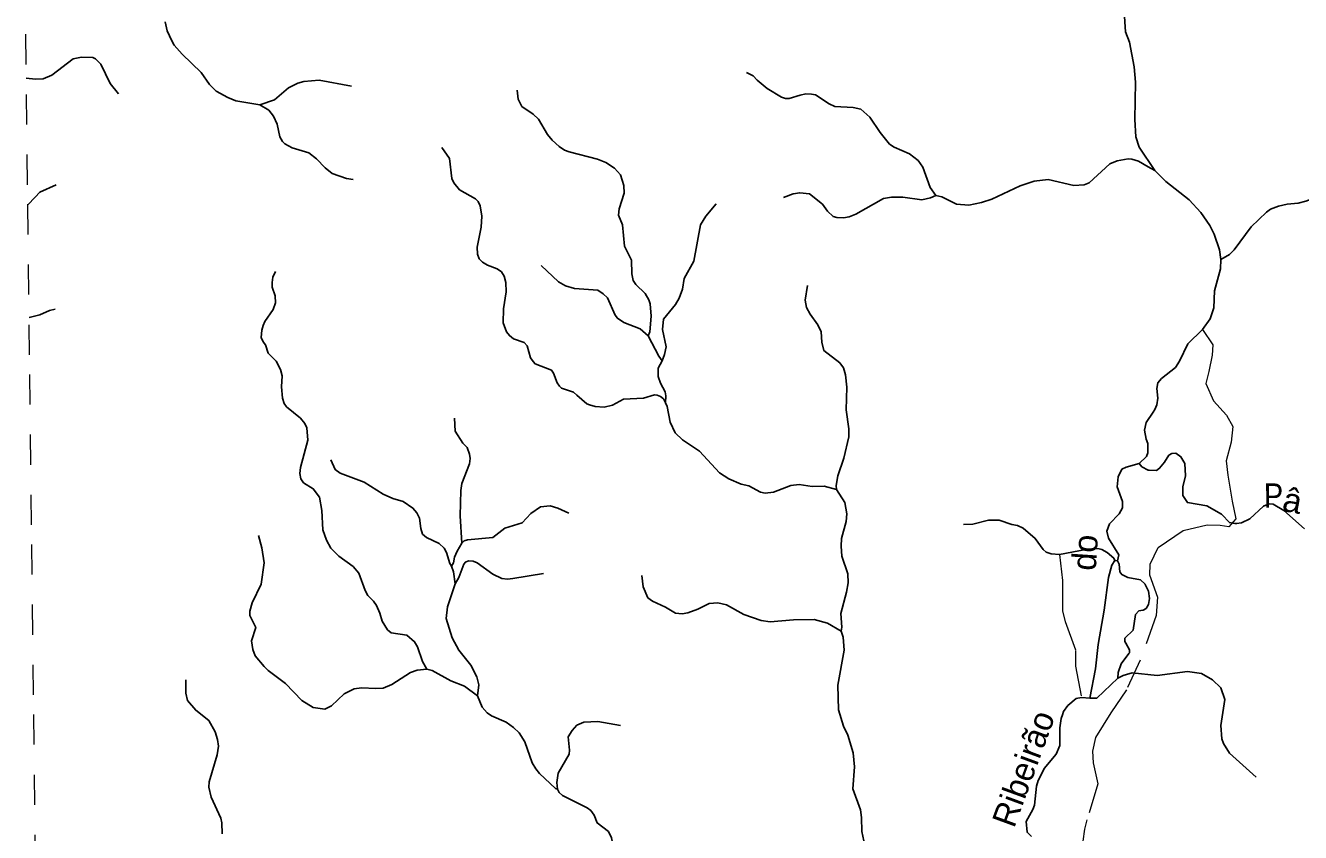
# Model space of a CAD drawing. Extents: x 320.3 to 346.3, y 7455.4 to 7483.3.
# Drawn here: x 320.388 to 324.622, y 7472.999 to 7475.68 of the extents above; entities that cross this region are included whole.
import ezdxf
from ezdxf.enums import TextEntityAlignment as Align

# ---------------------------------------------------------------- set-up
doc = ezdxf.new("R2010")
doc.units = 0
doc.header["$LTSCALE"] = 0.032
doc.linetypes.add('SHORT_DASHED', pattern=[2.7, 1.5, -1.2])
for name, color, linetype, lineweight in [('21', 7, 'SHORT_DASHED', 13), ('53', 7, 'SHORT_DASHED', 13), ('7', 7, 'Continuous', 25)]:
    doc.layers.add(name, color=color, linetype=linetype, lineweight=lineweight)
doc.layers.add('61', color=7, linetype='Continuous')

msp = doc.modelspace()

# ---------------------------------------------------------------- linework, layer by layer
at = {"layer": '21'}
for points in [[(324.2967, 7474.6697), (324.3315, 7474.6194), (324.3296, 7474.5852), (324.3182, 7474.53), (324.3086, 7474.4901), (324.3334, 7474.433), (324.3771, 7474.3854), (324.398, 7474.3474), (324.3923, 7474.296), (324.3752, 7474.2333), (324.3809, 7474.1857), (324.3961, 7474.1001), (324.4075, 7474.0412), (324.3847, 7474.0145), (324.3562, 7474.0183), (324.3125, 7474.0202), (324.2326, 7474.0012), (324.149, 7473.9442), (324.1224, 7473.889), (324.1205, 7473.8548), (324.1471, 7473.7806), (324.1433, 7473.7197), (324.0901, 7473.5714), (324.0445, 7473.4724), (323.9931, 7473.3963), (323.9418, 7473.3145), (323.9323, 7473.2688), (323.9342, 7473.2308), (323.9494, 7473.1604), (323.9133, 7473.0406), (323.9057, 7473.0101), (323.8943, 7472.9302)], [(323.8225, 7473.9227), (323.8321, 7473.8356), (323.8321, 7473.7955), (323.8321, 7473.7337), (323.8414, 7473.6997), (323.8754, 7473.604), (323.8754, 7473.5515), (323.8955, 7473.4469)]]:
    msp.add_lwpolyline(points, dxfattribs=at)
at = {"layer": '53'}
msp.add_lwpolyline([(320.5226, 7464.4161), (320.5159, 7464.9811), (320.5091, 7465.5461), (320.5024, 7466.1111), (320.4957, 7466.6761), (320.489, 7467.2411), (320.4823, 7467.806), (320.4756, 7468.371), (320.4689, 7468.936), (320.4621, 7469.501), (320.4554, 7470.066), (320.4487, 7470.6309), (320.442, 7471.1959), (320.4353, 7471.7609), (320.4286, 7472.3259), (320.4219, 7472.8909), (320.4152, 7473.4558), (320.4085, 7474.0208), (320.4018, 7474.5858), (320.3951, 7475.1508), (320.3884, 7475.7157)], dxfattribs=at)
at = {"layer": '7'}
msp.add_line((324.0056, 7473.9028), (324.0144, 7473.9013), dxfattribs=at)
for points in [[(324.037, 7475.7261), (324.0409, 7475.6592), (324.0545, 7475.6247), (324.0703, 7475.5421), (324.0741, 7475.4921), (324.0724, 7475.3681), (324.0752, 7475.3102), (324.0869, 7475.2757), (324.139, 7475.1987)], [(320.852, 7475.692), (320.8591, 7475.6623), (320.874, 7475.629), (320.8826, 7475.6144), (320.9091, 7475.5843), (320.9717, 7475.5236), (320.9992, 7475.4841), (321.0217, 7475.4612), (321.0601, 7475.4405), (321.0871, 7475.4294), (321.1668, 7475.4168)], [(320.6968, 7475.4532), (320.67, 7475.4869), (320.6384, 7475.5509), (320.6206, 7475.5695), (320.6121, 7475.5741), (320.574, 7475.5743), (320.5468, 7475.569), (320.4754, 7475.5145), (320.4473, 7475.5031), (320.4219, 7475.5011), (320.3909, 7475.5048)], [(321.1668, 7475.4168), (321.2158, 7475.4326), (321.2614, 7475.4731), (321.2928, 7475.4888), (321.313, 7475.4943), (321.3631, 7475.4983), (321.4715, 7475.4782)], [(323.4119, 7475.1155), (323.393, 7475.1416), (323.3685, 7475.209), (323.3528, 7475.2311), (323.3243, 7475.2533), (323.2732, 7475.2754), (323.2577, 7475.2857), (323.2262, 7475.3245), (323.1923, 7475.3748), (323.1621, 7475.4017), (323.1371, 7475.4069), (323.0761, 7475.4111), (323.0577, 7475.4191), (323.0117, 7475.449), (322.9983, 7475.4519), (322.9793, 7475.4526), (322.9606, 7475.4485), (322.9242, 7475.4373), (322.9119, 7475.4377), (322.8985, 7475.4416), (322.8509, 7475.4711), (322.8185, 7475.4988), (322.8047, 7475.5131), (322.7825, 7475.5232)], [(322.4559, 7474.6485), (322.4612, 7474.6621), (322.4664, 7474.7141), (322.4629, 7474.7548), (322.4587, 7474.7686), (322.4463, 7474.79), (322.4156, 7474.8197), (322.4065, 7474.8332), (322.4021, 7474.8551), (322.4003, 7474.9006), (322.3774, 7474.9472), (322.3715, 7475.0175), (322.3576, 7475.0497), (322.36, 7475.0706), (322.3765, 7475.1229), (322.3753, 7475.148), (322.3647, 7475.1843), (322.3445, 7475.2062), (322.316, 7475.2251), (322.2877, 7475.2355), (322.1941, 7475.2604), (322.1781, 7475.2662), (322.1606, 7475.2777), (322.1373, 7475.2993), (322.1224, 7475.3182), (322.0922, 7475.3686), (322.0742, 7475.3853), (322.0361, 7475.4109), (322.0242, 7475.4352), (322.021, 7475.4645)], [(321.1668, 7475.4168), (321.196, 7475.3981), (321.2115, 7475.3784), (321.2236, 7475.3521), (321.2335, 7475.3104), (321.2415, 7475.2945), (321.2495, 7475.2866), (321.2744, 7475.2733), (321.329, 7475.2569), (321.3549, 7475.2374), (321.3832, 7475.2068), (321.4063, 7475.1885), (321.4546, 7475.1715), (321.4764, 7475.1684)], [(322.5142, 7474.4266), (322.5076, 7474.4393), (322.4971, 7474.4473), (322.486, 7474.4521), (322.477, 7474.4531), (322.4403, 7474.4415), (322.3739, 7474.4387), (322.3377, 7474.4184), (322.31, 7474.4115), (322.28, 7474.4141), (322.2612, 7474.4192), (322.2526, 7474.4232), (322.2188, 7474.4521), (322.2083, 7474.4613), (322.1689, 7474.4754), (322.1617, 7474.4813), (322.1545, 7474.4926), (322.1423, 7474.5247), (322.1357, 7474.5343), (322.0809, 7474.5555), (322.0739, 7474.5632), (322.0649, 7474.5759), (322.0541, 7474.6156), (322.0445, 7474.627), (322.0086, 7474.6391), (321.9952, 7474.6498), (321.9854, 7474.6627), (321.9747, 7474.6923), (321.9763, 7474.7383), (321.9846, 7474.7948), (321.9833, 7474.8264), (321.978, 7474.8466), (321.9689, 7474.8613), (321.9551, 7474.8719), (321.9223, 7474.8842), (321.9064, 7474.8932), (321.8954, 7474.9052), (321.8895, 7474.9201), (321.888, 7474.9434), (321.9018, 7475.0099), (321.9035, 7475.0463), (321.8987, 7475.0807), (321.8917, 7475.0948), (321.8828, 7475.1045), (321.8302, 7475.1337), (321.8107, 7475.1575), (321.8041, 7475.1719), (321.7966, 7475.2384), (321.7708, 7475.2746)], [(324.139, 7475.1987), (324.1168, 7475.2106), (324.085, 7475.2292), (324.0622, 7475.2354), (324.0504, 7475.2364), (324.014, 7475.2306), (323.9896, 7475.22), (323.9212, 7475.1571), (323.9043, 7475.1504), (323.8697, 7475.1485), (323.784, 7475.1677), (323.7378, 7475.163), (323.6917, 7475.1472), (323.5979, 7475.1027), (323.5635, 7475.0915), (323.5216, 7475.083), (323.4796, 7475.0864), (323.4315, 7475.1112), (323.4119, 7475.1155)], [(324.139, 7475.1987), (324.175, 7475.1617), (324.2532, 7475.1011), (324.292, 7475.0591), (324.3216, 7475.0149), (324.336, 7474.9861), (324.353, 7474.9342), (324.3579, 7474.9023)], [(320.49, 7475.1507), (320.4364, 7475.126), (320.4202, 7475.1094), (320.3959, 7475.0844)], [(322.9052, 7475.1081), (322.9381, 7475.1206), (322.9596, 7475.1244), (322.9915, 7475.1204), (323.0352, 7475.0863), (323.0519, 7475.0627), (323.0706, 7475.0456), (323.0825, 7475.0418), (323.1054, 7475.0409), (323.1236, 7475.0442), (323.1462, 7475.053), (323.2379, 7475.1046), (323.2641, 7475.1093), (323.3018, 7475.1093), (323.3653, 7475.1008), (323.3935, 7475.1075), (323.4119, 7475.1155)], [(324.3579, 7474.9023), (324.3869, 7474.919), (324.4023, 7474.9342), (324.4588, 7475.0108), (324.5093, 7475.0597), (324.523, 7475.0694), (324.5498, 7475.0802), (324.5778, 7475.0862), (324.6152, 7475.0894), (324.64, 7475.096), (324.7074, 7475.1214), (324.7235, 7475.1318), (324.7492, 7475.1411)], [(322.5031, 7474.5663), (322.5102, 7474.5874), (322.5165, 7474.6128), (322.5041, 7474.6696), (322.5072, 7474.7037), (322.547, 7474.7528), (322.5592, 7474.7742), (322.5701, 7474.8037), (322.5761, 7474.8395), (322.6075, 7474.8969), (322.6305, 7475.0181), (322.6474, 7475.0462), (322.6815, 7475.0872)], [(321.7215, 7473.5414), (321.707, 7473.5669), (321.6907, 7473.6156), (321.6807, 7473.6327), (321.6547, 7473.6539), (321.6027, 7473.6626), (321.5903, 7473.6726), (321.5727, 7473.7005), (321.5654, 7473.727), (321.5537, 7473.7527), (321.5444, 7473.767), (321.5254, 7473.7867), (321.516, 7473.8028), (321.4948, 7473.8601), (321.4769, 7473.8822), (321.4291, 7473.9166), (321.4025, 7473.9434), (321.388, 7473.9705), (321.3761, 7474.0045), (321.373, 7474.0681), (321.3647, 7474.1129), (321.3439, 7474.1406), (321.3116, 7474.161), (321.3029, 7474.1739), (321.299, 7474.1917), (321.302, 7474.2118), (321.3259, 7474.3026), (321.3228, 7474.3429), (321.3163, 7474.3575), (321.3011, 7474.3755), (321.2555, 7474.4133), (321.2479, 7474.4241), (321.2424, 7474.4415), (321.239, 7474.4799), (321.241, 7474.5165), (321.2356, 7474.5371), (321.2212, 7474.5645), (321.1942, 7474.5911), (321.1857, 7474.6187), (321.1779, 7474.6285), (321.1714, 7474.6428), (321.1728, 7474.6673), (321.1772, 7474.6832), (321.1834, 7474.6969), (321.2107, 7474.7368), (321.2186, 7474.7583), (321.2178, 7474.7814), (321.2078, 7474.811), (321.2076, 7474.8256), (321.21, 7474.8437), (321.2189, 7474.8627)], [(322.4559, 7474.6485), (322.4296, 7474.6726), (322.3759, 7474.6934), (322.354, 7474.7074), (322.3465, 7474.7178), (322.3206, 7474.7747), (322.307, 7474.7887), (322.2894, 7474.8009), (322.2112, 7474.8063), (322.1821, 7474.8151), (322.1585, 7474.8281), (322.1007, 7474.882)], [(324.0863, 7474.2242), (324.1106, 7474.2483), (324.1156, 7474.2606), (324.1157, 7474.2909), (324.1097, 7474.3051), (324.1039, 7474.3352), (324.1098, 7474.3607), (324.1328, 7474.395), (324.1392, 7474.4046), (324.1459, 7474.4195), (324.1482, 7474.4413), (324.1451, 7474.4738), (324.1484, 7474.4926), (324.1612, 7474.5071), (324.2071, 7474.544), (324.2209, 7474.5648), (324.2479, 7474.6221), (324.2967, 7474.6697), (324.3229, 7474.7059), (324.3344, 7474.7417), (324.3369, 7474.7987), (324.3568, 7474.8712), (324.3579, 7474.9023)], [(323.0817, 7474.138), (323.0801, 7474.1522), (323.0859, 7474.1835), (323.1064, 7474.2429), (323.1231, 7474.313), (323.1228, 7474.3395), (323.1136, 7474.4026), (323.1159, 7474.4783), (323.1111, 7474.5188), (323.1045, 7474.5424), (323.0924, 7474.5588), (323.0398, 7474.6), (323.0334, 7474.6277), (323.0312, 7474.6621), (323.0199, 7474.6849), (322.9939, 7474.7204), (322.9821, 7474.7431), (322.9779, 7474.7673), (322.9848, 7474.816)], [(320.4868, 7474.738), (320.4677, 7474.7334), (320.4363, 7474.7184), (320.4003, 7474.7099)], [(322.4559, 7474.6485), (322.492, 7474.5814), (322.5031, 7474.5663)], [(322.5031, 7474.5663), (322.4889, 7474.5413), (322.4894, 7474.5135), (322.4976, 7474.4914), (322.5122, 7474.4629), (322.5148, 7474.4499), (322.5142, 7474.4266)], [(323.0817, 7474.138), (323.0406, 7474.1499), (323.0008, 7474.148), (322.958, 7474.1549), (322.9303, 7474.152), (322.8721, 7474.1297), (322.8449, 7474.1265), (322.8289, 7474.13), (322.7902, 7474.1501), (322.7655, 7474.1565), (322.7238, 7474.1738), (322.6933, 7474.194), (322.6266, 7474.2657), (322.5701, 7474.3033), (322.5461, 7474.3271), (322.5296, 7474.3621), (322.5191, 7474.4139), (322.5142, 7474.4266)], [(321.8135, 7474.3752), (321.8155, 7474.3326), (321.8404, 7474.2924), (321.8547, 7474.2775), (321.8632, 7474.2563), (321.8646, 7474.2417), (321.8626, 7474.2238), (321.8377, 7474.1583), (321.8339, 7474.1346), (321.8321, 7474.0512), (321.8373, 7473.96)], [(321.4023, 7474.2368), (321.4172, 7474.2048), (321.4329, 7474.1926), (321.5133, 7474.163), (321.5763, 7474.1234), (321.608, 7474.1084), (321.6428, 7474.0981), (321.6749, 7474.0767), (321.6878, 7474.0607), (321.6966, 7474.0432), (321.7009, 7474.0088), (321.7068, 7473.9905), (321.7204, 7473.9786), (321.7625, 7473.9588), (321.7784, 7473.943), (321.7861, 7473.9292), (321.7971, 7473.8923), (321.8031, 7473.884)], [(324.0863, 7474.2242), (324.0959, 7474.2142), (324.1168, 7474.2028), (324.1195, 7474.2027), (324.1438, 7474.2017), (324.1544, 7474.2089), (324.1714, 7474.2287), (324.1854, 7474.2523), (324.195, 7474.2579), (324.2087, 7474.2588), (324.2251, 7474.2473), (324.2385, 7474.2248), (324.2404, 7474.1842), (324.2321, 7474.1467), (324.2318, 7474.1188), (324.2467, 7474.0949), (324.3112, 7474.0846), (324.3602, 7474.0567), (324.3612, 7474.0556), (324.3865, 7474.0282), (324.4039, 7474.0258), (324.4101, 7474.0249), (324.4268, 7474.028), (324.4539, 7474.0404), (324.4997, 7474.0825), (324.5183, 7474.0909), (324.5317, 7474.0896), (324.5673, 7474.0687), (324.6353, 7474.0078)], [(324.0144, 7473.9013), (324.0191, 7473.9214), (323.9852, 7473.9762), (323.9791, 7474.0002), (323.9886, 7474.0243), (324.0207, 7474.0576), (324.0318, 7474.0777), (324.0311, 7474.0963), (324.031, 7474.0986), (324.0141, 7474.1471), (324.0173, 7474.1805), (324.0297, 7474.2056), (324.0441, 7474.2127), (324.0863, 7474.2242)], [(323.0975, 7473.6679), (323.0998, 7473.6815), (323.096, 7473.7261), (323.1148, 7473.7971), (323.1199, 7473.8287), (323.1189, 7473.8586), (323.0996, 7473.9172), (323.0975, 7473.9499), (323.0986, 7473.9754), (323.1132, 7474.0324), (323.1158, 7474.058), (323.1096, 7474.0951), (323.0817, 7474.138)], [(322.1924, 7474.0598), (322.1557, 7474.0769), (322.1312, 7474.0841), (322.0983, 7474.0807), (322.0668, 7474.0583), (322.0383, 7474.0281), (321.9805, 7474.0104), (321.9399, 7473.9785), (321.8566, 7473.9717), (321.8454, 7473.9681), (321.8373, 7473.96)], [(324.0056, 7473.9028), (324.0024, 7473.9102), (323.9808, 7473.9289), (323.9631, 7473.9387), (323.9499, 7473.942), (323.9495, 7473.9421), (323.91, 7473.9392), (323.8225, 7473.9227), (323.7945, 7473.9247), (323.7778, 7473.9305), (323.7681, 7473.9391), (323.7415, 7473.976), (323.7012, 7474.0104), (323.683, 7474.0184), (323.6638, 7474.0217), (323.622, 7474.036), (323.5866, 7474.037), (323.5343, 7474.0229), (323.5038, 7474.022)], [(321.7215, 7473.5414), (321.6889, 7473.5377), (321.667, 7473.5303), (321.6047, 7473.4908), (321.5757, 7473.4783), (321.5523, 7473.4768), (321.5046, 7473.48), (321.4794, 7473.476), (321.4464, 7473.46), (321.4048, 7473.4194), (321.382, 7473.4085), (321.3441, 7473.4136), (321.3064, 7473.437), (321.252, 7473.4943), (321.1941, 7473.5375), (321.1808, 7473.5506), (321.1513, 7473.5861), (321.1431, 7473.6073), (321.1389, 7473.6358), (321.1532, 7473.6797), (321.1339, 7473.7199), (321.1338, 7473.7337), (321.1412, 7473.7618), (321.1712, 7473.824), (321.1809, 7473.8944), (321.1735, 7473.9447), (321.1618, 7473.9858)], [(321.8373, 7473.96), (321.8216, 7473.9336), (321.8133, 7473.9133), (321.8097, 7473.8946), (321.8031, 7473.884)], [(322.1087, 7473.8595), (322.0067, 7473.8423), (321.989, 7473.8406), (321.9703, 7473.8425), (321.9407, 7473.8568), (321.8879, 7473.8947), (321.8755, 7473.9002), (321.8591, 7473.9011), (321.8493, 7473.8969), (321.8444, 7473.8906), (321.8271, 7473.8461), (321.8153, 7473.8246)], [(323.9232, 7473.4454), (323.9421, 7473.5423), (323.951, 7473.6236), (323.971, 7473.7376), (323.9849, 7473.8464), (323.9962, 7473.8874), (324.0056, 7473.9028)], [(324.0162, 7473.5116), (324.0165, 7473.5307), (324.0269, 7473.5592), (324.0528, 7473.5936), (324.0545, 7473.5958), (324.0543, 7473.6058), (324.042, 7473.6279), (324.0389, 7473.6335), (324.0392, 7473.6442), (324.0668, 7473.6707), (324.0746, 7473.7231), (324.0856, 7473.7348), (324.0991, 7473.7372), (324.0995, 7473.7374), (324.1103, 7473.7431), (324.1179, 7473.7562), (324.1214, 7473.776), (324.1175, 7473.8004), (324.107, 7473.8225), (324.1065, 7473.8235), (324.091, 7473.8381), (324.0494, 7473.8462), (324.0294, 7473.8556), (324.023, 7473.8653), (324.0201, 7473.8907), (324.0144, 7473.9013)], [(321.8153, 7473.8246), (321.8094, 7473.865), (321.8031, 7473.884)], [(323.0975, 7473.6679), (323.052, 7473.6943), (323.0077, 7473.7061), (322.939, 7473.7056), (322.8609, 7473.6992), (322.8316, 7473.7029), (322.7744, 7473.7231), (322.7158, 7473.7557), (322.6871, 7473.7623), (322.6591, 7473.7592), (322.6212, 7473.7406), (322.5876, 7473.7285), (322.5696, 7473.7257), (322.5471, 7473.7279), (322.514, 7473.7476), (322.4702, 7473.7677), (322.4547, 7473.7785), (322.4392, 7473.8153), (322.4346, 7473.8522)], [(321.8153, 7473.8246), (321.79, 7473.7488), (321.7855, 7473.7094), (321.8054, 7473.6458), (321.8278, 7473.6049), (321.8669, 7473.5548), (321.8877, 7473.5163), (321.8944, 7473.4896), (321.8895, 7473.4527)], [(323.1827, 7472.925), (323.1653, 7473.0019), (323.1648, 7473.0483), (323.1611, 7473.0744), (323.136, 7473.1439), (323.1415, 7473.2168), (323.1365, 7473.2634), (323.1193, 7473.3217), (323.1046, 7473.3518), (323.088, 7473.4059), (323.0865, 7473.4886), (323.107, 7473.6045), (323.1035, 7473.6483), (323.0975, 7473.6679)], [(321.8895, 7473.4527), (321.8463, 7473.4846), (321.8005, 7473.503), (321.7391, 7473.5366), (321.7215, 7473.5414)], [(324.0162, 7473.5116), (323.9457, 7473.4449), (323.9232, 7473.4454)], [(324.0162, 7473.5116), (324.0338, 7473.5205), (324.0447, 7473.5238), (324.0633, 7473.5295), (324.1461, 7473.5208), (324.2474, 7473.5342), (324.2941, 7473.5267), (324.3302, 7473.5064), (324.358, 7473.4796), (324.3715, 7473.4404), (324.3575, 7473.3539), (324.3614, 7473.31), (324.367, 7473.2944), (324.3865, 7473.2629), (324.4756, 7473.1829)], [(321.0417, 7472.9946), (321.0408, 7473.0309), (321.0368, 7473.0461), (321.0053, 7473.1159), (320.9977, 7473.149), (320.9983, 7473.1675), (321.0252, 7473.2564), (321.0288, 7473.2858), (321.0262, 7473.3083), (321.0185, 7473.3334), (320.9973, 7473.3709), (320.954, 7473.405), (320.9269, 7473.4371), (320.9204, 7473.4617), (320.9212, 7473.5063)], [(322.1552, 7473.1424), (322.1482, 7473.1454), (322.0948, 7473.1954), (322.0826, 7473.2108), (322.0707, 7473.2308), (322.0462, 7473.3), (322.0281, 7473.3303), (322.0094, 7473.3479), (321.9849, 7473.3649), (321.9363, 7473.3859), (321.9211, 7473.3959), (321.9048, 7473.4151), (321.8895, 7473.4527)], [(323.7291, 7472.9856), (323.7147, 7472.9999), (323.7111, 7473.0359), (323.7337, 7473.0748), (323.7387, 7473.0895), (323.7457, 7473.1524), (323.7517, 7473.1716), (323.7711, 7473.2104), (323.7715, 7473.2112), (323.8107, 7473.2586), (323.8228, 7473.2879), (323.823, 7473.3213), (323.8232, 7473.3462), (323.8281, 7473.378), (323.8322, 7473.3903), (323.8358, 7473.4011), (323.8496, 7473.4205), (323.8778, 7473.4436), (323.8955, 7473.4469), (323.9232, 7473.4454)], [(322.3646, 7473.3542), (322.2895, 7473.3672), (322.243, 7473.3655), (322.2198, 7473.3553), (322.2037, 7473.3374), (322.1907, 7473.3165), (322.1952, 7473.272), (322.1936, 7473.2586), (322.1572, 7473.1965), (322.1526, 7473.1645), (322.1552, 7473.1424)], [(322.1552, 7473.1424), (322.1604, 7473.1318), (322.1715, 7473.1213), (322.2539, 7473.0811), (322.2659, 7473.0718), (322.2766, 7473.0569), (322.2873, 7473.0307), (322.324, 7473.0019), (322.3344, 7472.9809), (322.3435, 7472.939), (322.3543, 7472.9237), (322.3611, 7472.9198), (322.3997, 7472.9162), (322.4175, 7472.9075), (322.4386, 7472.8696), (322.4536, 7472.8125), (322.4604, 7472.7727)]]:
    msp.add_lwpolyline(points, dxfattribs=at)

# ---------------------------------------------------------------- texts
at = {"layer": '61'}
for s, rotation, width, p in [('P', 0.328, 0.9, (324.533, 7474.0785)), ('â', 349.189, 1.05, (324.5889, 7474.0624))]:
    msp.add_text(s, height=0.08, rotation=rotation, dxfattribs=dict(at, width=width)).set_placement(p, align=Align.CENTER)
for s, rotation, p in [('do', 86.179, (323.9462, 7473.9265)), ('Ribeirão', 69.844, (323.74, 7473.1976))]:
    msp.add_text(s, height=0.08, rotation=rotation, dxfattribs=at).set_placement(p, align=Align.CENTER)

doc.saveas('drawing.dxf')
